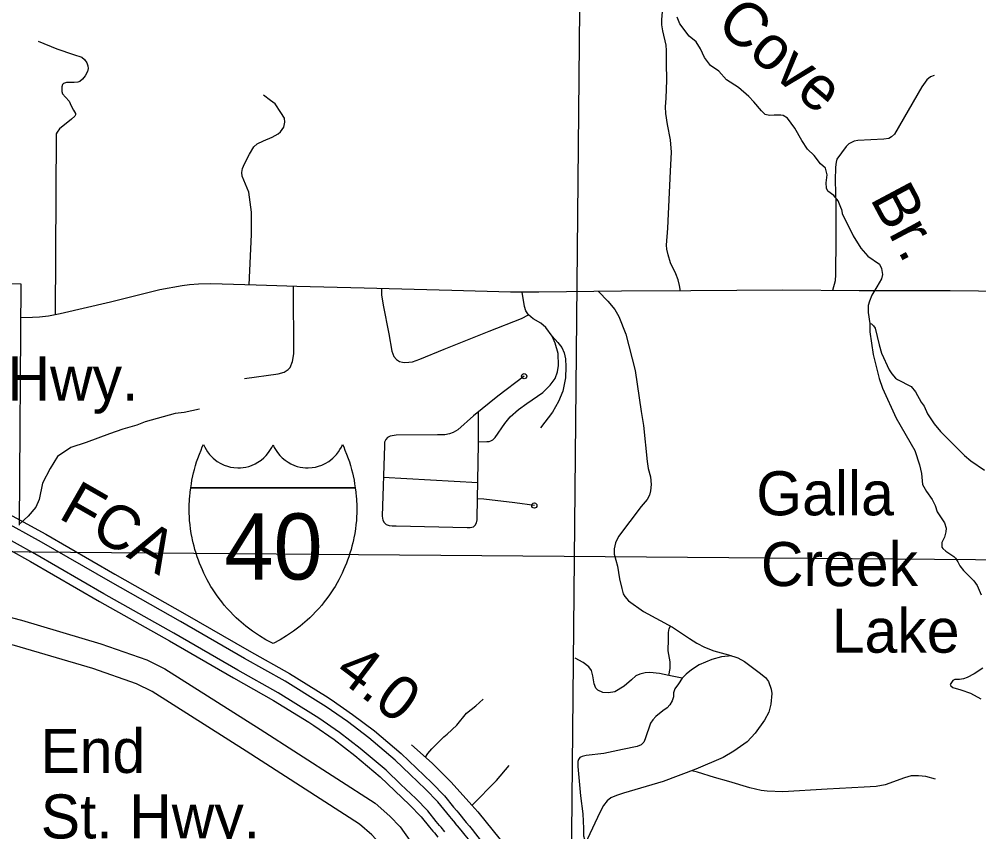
# Model space of a CAD drawing. Extents: x 1374139 to 1377472, y 1168351 to 1170484.
# Drawn here: x 1375599.1 to 1375783.1, y 1169248.4 to 1169404.2 of the extents above; entities that cross this region are included whole.
import ezdxf

# ---------------------------------------------------------------- set-up
doc = ezdxf.new("R2010")
doc.units = 0
doc.layers.add('Default', color=7, linetype='Continuous')

msp = doc.modelspace()

# ---------------------------------------------------------------- linework, layer by layer
at = {"layer": 'Default'}
for points in [[(1375546.74, 1169406.15), (1375546.32, 1169353.56), (1375599.42, 1169353.42), (1375599.06, 1169307.19)], [(1375706.53, 1169406.08), (1375700.78, 1168813.25)], [(1375725.85, 1169352.06), (1375725.68, 1169353.13), (1375725.43, 1169354.18), (1375724.95, 1169355.36), (1375723.98, 1169357.47), (1375723.49, 1169359), (1375723.25, 1169360.08), (1375723.21, 1169360.87), (1375723.42, 1169364.1), (1375723.98, 1169375.03), (1375724.15, 1169378.68), (1375723.98, 1169381.04), (1375723.39, 1169383.99), (1375723.04, 1169386.07), (1375723.01, 1169387.39), (1375723.11, 1169389.02), (1375723.25, 1169392.49), (1375723.18, 1169395.75), (1375723.21, 1169398.15), (1375723.11, 1169399.2), (1375722.49, 1169401.95), (1375722.31, 1169403.06), (1375722.28, 1169404.1), (1375722.42, 1169405.55)], [(1375756.73, 1169367.76), (1375756.11, 1169369.33), (1375755.25, 1169370.36), (1375754.14, 1169371.23), (1375753.85, 1169371.8), (1375753.81, 1169372.79), (1375753.97, 1169374.32), (1375753.64, 1169375.63), (1375752.7, 1169376.46), (1375751.5, 1169378.02), (1375750.19, 1169379.26), (1375749.16, 1169380.9), (1375747.8, 1169383.29), (1375746.36, 1169385.22), (1375745.58, 1169385.68), (1375745.12, 1169385.76), (1375743.85, 1169385.76), (1375742.9, 1169385.72), (1375742.08, 1169385.88), (1375741.38, 1169386.62), (1375739.9, 1169388.35), (1375738.99, 1169389.34), (1375737, 1169391.09), (1375734.69, 1169392.57), (1375733.21, 1169394.22), (1375731.65, 1169395.29), (1375730.5, 1169396.85), (1375729.68, 1169398.5), (1375728.85, 1169399.82), (1375727.54, 1169400.89), (1375725.73, 1169403.28), (1375725.23, 1169404.59)], [(1375602.75, 1169399.98), (1375606.32, 1169398.5), (1375609.49, 1169397.42), (1375611.07, 1169396.92), (1375611.62, 1169396.45), (1375612.05, 1169395.8), (1375612.23, 1169395.22), (1375612.3, 1169394.72), (1375612.19, 1169394.14), (1375611.72, 1169393.31), (1375611.22, 1169392.67), (1375610.75, 1169392.23), (1375610.35, 1169392.09), (1375609.63, 1169392.05), (1375608.16, 1169392.02), (1375607.58, 1169391.87), (1375607.4, 1169391.66), (1375607.26, 1169391.19), (1375607.26, 1169390.32), (1375607.4, 1169389.85), (1375607.94, 1169389.21), (1375608.66, 1169388.48), (1375608.88, 1169387.98), (1375609.17, 1169387.33), (1375609.53, 1169386.75), (1375609.89, 1169386.11), (1375609.89, 1169385.85), (1375609.74, 1169385.56), (1375609.13, 1169385.02), (1375606.79, 1169383.15), (1375606.35, 1169382.54), (1375606.21, 1169382.18)], [(1375774.48, 1169393.36), (1375773.8, 1169393.1), (1375773.12, 1169392.57), (1375772.12, 1169391.21), (1375766.87, 1169382.12), (1375766.33, 1169381.61), (1375765.81, 1169381.32), (1375764.87, 1169381.16), (1375759.88, 1169380.9), (1375759.17, 1169380.8), (1375758.65, 1169380.56), (1375758.15, 1169380.3), (1375757.65, 1169379.77), (1375755.86, 1169377.33), (1375755.71, 1169376.75), (1375755.6, 1169375.83), (1375755.52, 1169373.23), (1375755.63, 1169368.67), (1375755.65, 1169362.04), (1375755.6, 1169355.25), (1375755.52, 1169354.02), (1375755.02, 1169352.15)], [(1375643.16, 1169353.25), (1375643.63, 1169362.92), (1375643.61, 1169367.17), (1375643.1, 1169371.04), (1375641.86, 1169374.07), (1375641.76, 1169374.78), (1375641.89, 1169375.52), (1375642.3, 1169376.46), (1375643.24, 1169378.27), (1375644.08, 1169379.72), (1375644.69, 1169380.29), (1375645.9, 1169380.87), (1375647.61, 1169381.54), (1375648.72, 1169382.18), (1375649.16, 1169382.61), (1375649.8, 1169383.46), (1375650, 1169384.4), (1375649.93, 1169385.17), (1375649.26, 1169386.31), (1375648.15, 1169387.92), (1375647.27, 1169388.56), (1375645.93, 1169389.6)], [(1375606.21, 1169382.18), (1375605.97, 1169347.51)], [(1375756.73, 1169367.76), (1375756.87, 1169366.9), (1375758.97, 1169362.66), (1375760.45, 1169360.31), (1375761.8, 1169358.77), (1375764.02, 1169357.22), (1375764.38, 1169356.41), (1375764.57, 1169355.23), (1375764.39, 1169354.38), (1375763.48, 1169352.86)], [(1375793.77, 1169351.94), (1375777.57, 1169352.13), (1375766.42, 1169352.1), (1375760.13, 1169352.12), (1375745.47, 1169352.21), (1375727.86, 1169352.07), (1375714.56, 1169352.02), (1375698.74, 1169351.85), (1375693.28, 1169351.85), (1375682.05, 1169352.17), (1375665.22, 1169352.64), (1375652.34, 1169352.93), (1375648.49, 1169353.06), (1375644.54, 1169353.21), (1375635.86, 1169353.47), (1375633.47, 1169353.37), (1375631.74, 1169353.26), (1375630.33, 1169353.09), (1375626.04, 1169352.31), (1375616.62, 1169349.96), (1375606.95, 1169347.71), (1375604.73, 1169347.25), (1375603, 1169347.06), (1375601.63, 1169346.96), (1375599.37, 1169346.92)], [(1375642.28, 1169335.3), (1375648.77, 1169336.17), (1375649.9, 1169336.51), (1375650.63, 1169336.99), (1375651.02, 1169337.42), (1375651.5, 1169338.55), (1375651.72, 1169340.02), (1375651.71, 1169352.95)], [(1375668.58, 1169352.55), (1375668.58, 1169351.33), (1375668.84, 1169349.38), (1375669.93, 1169343.89), (1375670.51, 1169340.55), (1375670.94, 1169339.52), (1375671.45, 1169338.94), (1375672, 1169338.57), (1375672.55, 1169338.4), (1375673, 1169338.37), (1375673.81, 1169338.4), (1375674.5, 1169338.51), (1375675.91, 1169339.03), (1375680.56, 1169340.93), (1375689.18, 1169344.38), (1375695.41, 1169346.82), (1375696.74, 1169347.52)], [(1375687.13, 1169323.16), (1375688.77, 1169323.19), (1375689.2, 1169323.25), (1375689.51, 1169323.33), (1375689.89, 1169323.53), (1375690.32, 1169323.97), (1375692.19, 1169326.64), (1375693.22, 1169327.93), (1375694.83, 1169329.34), (1375696.44, 1169330.52), (1375699.47, 1169332.61), (1375700.88, 1169333.99), (1375701.83, 1169335.31), (1375702.31, 1169336.58), (1375702.46, 1169337.78), (1375702.43, 1169340.08), (1375701.85, 1169342.09), (1375701.28, 1169343.39), (1375700.04, 1169345.06), (1375699.12, 1169345.88), (1375697.63, 1169346.74), (1375696.74, 1169347.52), (1375696.19, 1169348.24), (1375695.94, 1169349.07), (1375695.53, 1169351.85)], [(1375710.16, 1169351.97), (1375711.93, 1169350.14), (1375713.27, 1169348.52), (1375714.02, 1169347.21), (1375715.36, 1169343.82), (1375717.17, 1169336.85), (1375718.34, 1169328.95), (1375718.8, 1169326.26), (1375719.45, 1169319.37), (1375719.68, 1169318.03), (1375720.1, 1169316.45), (1375720.24, 1169314.96), (1375720.15, 1169313.75), (1375719.91, 1169312.92), (1375719.5, 1169312.13), (1375718.34, 1169310.78), (1375713.97, 1169305.02), (1375713.41, 1169303.81), (1375713.18, 1169302.65), (1375713.13, 1169301.62), (1375713.78, 1169299.3), (1375714.2, 1169296.88), (1375714.62, 1169295.02), (1375714.9, 1169294.04), (1375715.22, 1169293.53), (1375715.87, 1169292.65), (1375718.8, 1169290.65), (1375724.33, 1169287.63), (1375727.58, 1169285.49), (1375729.02, 1169284.57), (1375730.5, 1169283.82), (1375732.27, 1169283.12), (1375735.06, 1169282.33), (1375736.87, 1169281.78), (1375738.17, 1169281.03), (1375740.95, 1169278.94), (1375742.16, 1169277.97), (1375742.72, 1169277.22), (1375743.28, 1169275.74), (1375743.37, 1169274.9), (1375743.18, 1169272.9), (1375742.81, 1169271.37), (1375741.98, 1169269.79), (1375740.21, 1169267.31), (1375738.68, 1169265.68), (1375736.12, 1169263.87), (1375734.03, 1169262.66), (1375728.83, 1169260.39), (1375722.56, 1169258.06), (1375714.94, 1169255.83), (1375713.6, 1169255.37), (1375712.53, 1169254.9), (1375711.83, 1169254.35), (1375711.09, 1169253.42), (1375710.39, 1169252.12), (1375707.1, 1169245.01)], [(1375763.48, 1169352.86), (1375762.52, 1169351.25), (1375762.07, 1169350.09), (1375761.87, 1169349.29), (1375761.82, 1169347.96), (1375762.17, 1169345.82)], [(1375762.17, 1169345.82), (1375762.15, 1169344.24), (1375762.83, 1169339.88), (1375763.94, 1169335.27), (1375764.61, 1169333.42), (1375767.2, 1169327.71), (1375770.77, 1169321.48), (1375771.67, 1169318.77), (1375772.05, 1169317.06), (1375772.28, 1169314.99), (1375773.04, 1169313.61), (1375774.13, 1169312.09), (1375774.66, 1169310.98), (1375775.05, 1169309.75), (1375776.46, 1169307.61), (1375776.78, 1169306.58), (1375776.76, 1169305.89), (1375776.48, 1169304.91), (1375775.95, 1169303.89), (1375775.99, 1169302.99), (1375776.17, 1169302.69), (1375776.73, 1169302.2), (1375778.29, 1169301.16), (1375778.6, 1169300.84), (1375779.05, 1169300.17), (1375779.43, 1169299.38), (1375780.13, 1169298.49), (1375782.08, 1169296.54), (1375782.76, 1169295.59), (1375783.48, 1169293.84)], [(1375762.17, 1169345.82), (1375762.49, 1169345.79), (1375762.9, 1169345.4), (1375763.19, 1169344.93), (1375763.93, 1169341.77), (1375764.41, 1169340.18), (1375765.86, 1169336.97), (1375766.36, 1169336.16), (1375767.1, 1169335.35), (1375767.49, 1169335.1), (1375770.1, 1169333.78), (1375770.92, 1169332.74), (1375772.01, 1169330.76), (1375772.55, 1169330.01), (1375773.24, 1169328.54), (1375774.47, 1169326.62), (1375775.7, 1169325.11), (1375780.31, 1169320.55), (1375781.55, 1169319.53), (1375784.15, 1169317.75)], [(1375701.28, 1169343.39), (1375702.34, 1169342.21), (1375703.15, 1169341.21), (1375703.58, 1169340.2), (1375703.81, 1169339.05), (1375703.89, 1169337.53), (1375703.84, 1169335.43), (1375703.32, 1169332.87), (1375702.49, 1169330.91), (1375701.34, 1169328.85), (1375699.04, 1169325.86)], [(1375695.9, 1169335.74), (1375690.85, 1169331.91), (1375686.16, 1169328.17), (1375683.17, 1169325.47), (1375682.26, 1169324.95), (1375681.57, 1169324.7), (1375680.68, 1169324.52), (1375679.3, 1169324.52), (1375671.37, 1169324.41), (1375670.22, 1169324.26), (1375669.73, 1169323.98), (1375669.38, 1169323.63), (1375669.15, 1169323.09), (1375669.1, 1169322.45), (1375668.66, 1169308.92), (1375668.78, 1169308.15), (1375669.04, 1169307.72), (1375669.44, 1169307.34), (1375670.01, 1169307.11), (1375670.59, 1169307.06), (1375671.34, 1169307.06), (1375685, 1169306.71), (1375685.55, 1169306.71), (1375686.18, 1169306.88), (1375686.53, 1169307.17), (1375686.76, 1169307.6), (1375686.87, 1169308.18), (1375686.9, 1169308.61), (1375687.13, 1169322.75), (1375687.16, 1169328.97)], [(1375633.63, 1169329.41), (1375630.73, 1169328.79), (1375628.99, 1169328.59), (1375623.24, 1169326.97), (1375621.64, 1169326.32), (1375618.95, 1169325.57), (1375616.39, 1169324.72), (1375611.93, 1169323.05), (1375608.98, 1169322.08), (1375606.41, 1169320.37), (1375605.04, 1169318.02), (1375603.59, 1169315.22), (1375602.93, 1169312.12), (1375602.27, 1169310.63), (1375600.82, 1169308.89), (1375599.3, 1169307.5)], [(1375631.98, 1169314.37), (1375632.1, 1169315.12), (1375632.21, 1169315.79), (1375632.39, 1169316.65), (1375632.52, 1169317.21), (1375632.69, 1169317.87), (1375632.91, 1169318.65), (1375633.11, 1169319.31), (1375633.34, 1169319.98), (1375633.64, 1169320.81), (1375633.95, 1169321.58), (1375634.2, 1169322.19), (1375634.42, 1169322.66), (1375634.65, 1169322.15), (1375634.92, 1169321.66), (1375635.21, 1169321.21), (1375635.6, 1169320.72), (1375635.9, 1169320.38), (1375636.28, 1169320.02), (1375636.65, 1169319.7), (1375637.07, 1169319.4), (1375637.72, 1169319.01), (1375638.39, 1169318.7), (1375639, 1169318.48), (1375639.6, 1169318.33), (1375640.24, 1169318.22), (1375640.99, 1169318.17), (1375641.49, 1169318.18), (1375642.05, 1169318.23), (1375642.55, 1169318.32), (1375643.09, 1169318.45), (1375643.63, 1169318.63), (1375644.36, 1169318.95), (1375644.87, 1169319.24), (1375645.45, 1169319.63), (1375646.01, 1169320.11), (1375646.42, 1169320.52), (1375646.89, 1169321.09), (1375647.27, 1169321.66), (1375647.5, 1169322.07), (1375647.75, 1169322.6)], [(1375647.75, 1169322.6), (1375648, 1169322.07), (1375648.22, 1169321.66), (1375648.61, 1169321.09), (1375649.08, 1169320.52), (1375649.49, 1169320.11), (1375650.05, 1169319.63), (1375650.63, 1169319.24), (1375651.14, 1169318.95), (1375651.87, 1169318.63), (1375652.41, 1169318.45), (1375652.95, 1169318.32), (1375653.45, 1169318.23), (1375654.01, 1169318.18), (1375654.51, 1169318.17), (1375655.26, 1169318.22), (1375655.9, 1169318.33), (1375656.5, 1169318.48), (1375657.11, 1169318.7), (1375657.78, 1169319.01), (1375658.43, 1169319.4), (1375658.84, 1169319.7), (1375659.22, 1169320.02), (1375659.6, 1169320.38), (1375659.9, 1169320.72), (1375660.29, 1169321.21), (1375660.58, 1169321.66), (1375660.85, 1169322.15), (1375661.08, 1169322.66), (1375661.3, 1169322.19), (1375661.55, 1169321.58), (1375661.86, 1169320.81), (1375662.16, 1169319.98), (1375662.39, 1169319.31), (1375662.59, 1169318.65), (1375662.81, 1169317.87), (1375662.98, 1169317.21), (1375663.11, 1169316.65), (1375663.29, 1169315.79), (1375663.4, 1169315.12), (1375663.52, 1169314.37)], [(1375668.9, 1169316.4), (1375687.01, 1169315.34)], [(1375647.75, 1169284.49), (1375646.37, 1169285.23), (1375645.15, 1169285.96), (1375643.81, 1169286.86), (1375642.57, 1169287.81), (1375641.2, 1169288.97), (1375640.69, 1169289.45), (1375640.11, 1169290.01), (1375639.58, 1169290.57), (1375638.99, 1169291.21), (1375638.41, 1169291.88), (1375637.93, 1169292.48), (1375637.41, 1169293.15), (1375636.93, 1169293.81), (1375636.52, 1169294.41), (1375636.16, 1169294.97), (1375635.86, 1169295.45), (1375635.47, 1169296.12), (1375635.16, 1169296.68), (1375634.83, 1169297.32), (1375634.5, 1169297.99), (1375634.21, 1169298.6), (1375633.95, 1169299.2), (1375633.68, 1169299.87), (1375633.44, 1169300.49), (1375633.22, 1169301.13), (1375633, 1169301.81), (1375632.79, 1169302.5), (1375632.61, 1169303.16), (1375632.45, 1169303.79), (1375632.32, 1169304.34), (1375632.24, 1169304.76), (1375632.09, 1169305.56), (1375631.94, 1169306.49), (1375631.85, 1169307.26), (1375631.77, 1169308.08), (1375631.73, 1169308.74), (1375631.7, 1169309.57), (1375631.69, 1169310.35), (1375631.71, 1169311.22), (1375631.73, 1169311.79), (1375631.76, 1169312.31), (1375631.79, 1169312.64), (1375631.87, 1169313.5), (1375631.98, 1169314.37)], [(1375631.98, 1169314.37), (1375663.52, 1169314.37)], [(1375663.52, 1169314.37), (1375631.98, 1169314.37)], [(1375663.52, 1169314.37), (1375663.63, 1169313.5), (1375663.71, 1169312.64), (1375663.74, 1169312.31), (1375663.77, 1169311.79), (1375663.79, 1169311.22), (1375663.81, 1169310.35), (1375663.8, 1169309.57), (1375663.77, 1169308.74), (1375663.73, 1169308.08), (1375663.65, 1169307.26), (1375663.56, 1169306.49), (1375663.41, 1169305.56), (1375663.26, 1169304.76), (1375663.18, 1169304.34), (1375663.05, 1169303.79), (1375662.89, 1169303.16), (1375662.71, 1169302.5), (1375662.5, 1169301.81), (1375662.28, 1169301.13), (1375662.05, 1169300.49), (1375661.82, 1169299.87), (1375661.55, 1169299.2), (1375661.29, 1169298.6), (1375661, 1169297.99), (1375660.67, 1169297.32), (1375660.34, 1169296.68), (1375660.03, 1169296.12), (1375659.64, 1169295.45), (1375659.34, 1169294.97), (1375658.98, 1169294.41), (1375658.57, 1169293.81), (1375658.09, 1169293.15), (1375657.57, 1169292.48), (1375657.09, 1169291.88), (1375656.51, 1169291.21), (1375655.92, 1169290.57), (1375655.39, 1169290.01), (1375654.81, 1169289.45), (1375654.3, 1169288.97), (1375652.93, 1169287.81), (1375651.68, 1169286.86), (1375650.35, 1169285.96), (1375649.13, 1169285.23), (1375647.75, 1169284.49)], [(1375697.85, 1169310.95), (1375694.12, 1169311.45), (1375688.14, 1169312.14), (1375686.96, 1169312.25)], [(1375596.34, 1169309.76), (1375604.2, 1169305.43), (1375617.45, 1169297.76), (1375630.86, 1169290.2), (1375643.15, 1169283.1), (1375650.93, 1169278.75), (1375657.83, 1169274.45), (1375658.91, 1169273.75), (1375663, 1169270.92), (1375667.19, 1169267.74), (1375672.3, 1169263.42), (1375675.25, 1169260.6), (1375678.17, 1169257.8), (1375680.62, 1169255.27), (1375682.35, 1169253.15), (1375682.96, 1169252.43), (1375683.3, 1169252.04), (1375684.06, 1169251.1)], [(1375682.72, 1169250.04), (1375682, 1169250.95), (1375681.67, 1169251.32), (1375681.05, 1169252.07), (1375679.35, 1169254.13), (1375676.97, 1169256.6), (1375674.07, 1169259.37), (1375671.16, 1169262.15), (1375666.12, 1169266.41), (1375662, 1169269.55), (1375657.96, 1169272.34), (1375656.92, 1169273.02), (1375650.06, 1169277.29), (1375642.31, 1169281.62), (1375630.02, 1169288.72), (1375616.61, 1169296.29), (1375603.36, 1169303.95), (1375595.5, 1169308.29)], [(1375680.69, 1169248.42), (1375680.01, 1169249.28), (1375679.7, 1169249.62), (1375679.04, 1169250.4), (1375677.4, 1169252.41), (1375675.14, 1169254.76), (1375672.28, 1169257.49), (1375669.43, 1169260.22), (1375664.49, 1169264.38), (1375660.48, 1169267.44), (1375656.52, 1169270.18), (1375655.52, 1169270.82), (1375648.74, 1169275.05), (1375641.02, 1169279.36), (1375628.73, 1169286.46), (1375615.32, 1169294.03), (1375602.08, 1169301.68), (1375594.21, 1169306.03)], [(1375924.39, 1169299.41), (1375198.69, 1169305.24)], [(1375593.37, 1169304.55), (1375601.24, 1169300.2), (1375614.47, 1169292.55), (1375627.89, 1169284.98), (1375640.18, 1169277.89), (1375647.87, 1169273.59), (1375654.61, 1169269.39), (1375655.57, 1169268.77), (1375659.48, 1169266.07), (1375663.43, 1169263.06), (1375668.29, 1169258.95), (1375671.1, 1169256.26), (1375673.94, 1169253.55), (1375676.13, 1169251.27), (1375677.74, 1169249.32), (1375678.41, 1169248.51), (1375678.71, 1169248.18), (1375679.36, 1169247.36)], [(1375582.23, 1169293.42), (1375599.56, 1169288.96), (1375614.74, 1169284.46), (1375623.57, 1169281.39), (1375627.03, 1169279.62), (1375645.31, 1169268.09), (1375667.32, 1169253.87), (1375670.13, 1169251.42), (1375672.12, 1169249.33), (1375681.28, 1169236.46), (1375693.31, 1169219.15), (1375703.09, 1169205.04), (1375708.96, 1169197.88), (1375713.03, 1169193.87), (1375719.04, 1169189.03), (1375727.51, 1169183.26)], [(1375724.53, 1169179.24), (1375716.06, 1169185.01), (1375709.7, 1169190.14), (1375705.26, 1169194.51), (1375699.09, 1169202.03), (1375689.2, 1169216.3), (1375677.19, 1169233.58), (1375668.25, 1169246.14), (1375666.67, 1169247.8), (1375664.31, 1169249.86), (1375642.62, 1169263.88), (1375624.56, 1169275.27), (1375621.6, 1169276.78), (1375613.21, 1169279.7), (1375598.22, 1169284.14), (1375581.02, 1169288.57)], [(1375726.21, 1169277.88), (1375723.65, 1169278.39), (1375723.87, 1169279.7), (1375723.87, 1169281), (1375723.52, 1169283.09), (1375723.57, 1169285.35), (1375723.57, 1169286.61), (1375723.7, 1169287.35), (1375723.93, 1169287.85)], [(1375723.65, 1169278.39), (1375721.83, 1169278.74), (1375720, 1169278.92), (1375719.09, 1169278.87), (1375718.05, 1169278.65), (1375717.31, 1169278.31), (1375716.48, 1169277.52), (1375715.09, 1169276.31), (1375713.26, 1169275.22), (1375712.09, 1169275.04), (1375710.96, 1169275.09), (1375710, 1169275.57), (1375709.66, 1169275.96), (1375709.31, 1169276.74), (1375709.05, 1169278.31), (1375708.83, 1169279.31), (1375708.31, 1169280.05), (1375707.18, 1169280.83), (1375705.7, 1169281.7)], [(1375735.68, 1169282.14), (1375733.72, 1169281.92), (1375731.85, 1169281.44), (1375729.46, 1169280.39), (1375727.98, 1169279.48), (1375726.98, 1169278.65), (1375726.2, 1169277.87), (1375725.46, 1169276.78), (1375724.77, 1169275.78), (1375724.55, 1169275.04), (1375724.51, 1169274.26), (1375724.29, 1169273.52), (1375723.85, 1169272.74), (1375723.29, 1169272.17), (1375722.51, 1169271.61), (1375721.12, 1169270.48), (1375720.55, 1169269.87), (1375720.12, 1169269.26), (1375719.07, 1169266.22), (1375718.81, 1169265.61), (1375718.33, 1169265.09), (1375717.59, 1169264.78), (1375714.73, 1169264.17), (1375711.16, 1169263.39), (1375707.81, 1169263)], [(1375783.8, 1169279.77), (1375782.16, 1169278.66), (1375780.8, 1169277.97), (1375780.09, 1169277.73), (1375779.33, 1169277.59), (1375778.43, 1169277.57), (1375778.05, 1169277.42), (1375777.57, 1169276.65), (1375777.68, 1169276.39), (1375778.09, 1169276.04), (1375779.64, 1169275.63), (1375781.45, 1169274.99), (1375783.42, 1169273.92)], [(1375681.14, 1169267.11), (1375682.97, 1169268.83), (1375684.86, 1169271.16), (1375686.66, 1169272.54), (1375688.05, 1169273.82)], [(1375677, 1169262.7), (1375677.4, 1169263.39), (1375678.2, 1169264.33), (1375680.53, 1169266.61), (1375681.14, 1169267.11)], [(1375674.28, 1169265.08), (1375678.28, 1169261.58), (1375681.93, 1169257.89), (1375685.88, 1169253.54), (1375687.04, 1169252.21), (1375691.3, 1169246.95), (1375694.39, 1169242.68), (1375696.26, 1169239.85), (1375697.95, 1169237.2), (1375699.99, 1169234.19)], [(1375707.81, 1169263), (1375706.99, 1169262.82), (1375706.6, 1169262.65), (1375706.29, 1169262.26), (1375706.21, 1169261.87), (1375706.21, 1169260.91), (1375706.68, 1169255.28), (1375707.12, 1169251.84), (1375707.25, 1169249.06), (1375707.29, 1169247.63), (1375707.47, 1169247.02), (1375707.77, 1169246.46)], [(1375685.92, 1169253.5), (1375690.6, 1169258.27), (1375693.01, 1169261.13)], [(1375774.75, 1169258.51), (1375772.91, 1169258.99), (1375771.48, 1169259.16), (1375770.12, 1169259.11), (1375768.82, 1169258.75), (1375765.08, 1169257.44), (1375763.36, 1169257.09), (1375761.05, 1169256.97), (1375753.99, 1169256.61), (1375745.46, 1169256.08), (1375742.51, 1169256.18), (1375741.35, 1169256.33), (1375739.19, 1169256.84), (1375735.13, 1169258.02), (1375732.37, 1169258.79), (1375729.11, 1169259.83), (1375728.05, 1169260.1)], [(1375683.99, 1169251.17), (1375684.81, 1169250.21), (1375685.39, 1169249.5), (1375685.93, 1169248.84), (1375686.57, 1169248.03), (1375687.45, 1169246.88), (1375689.02, 1169244.82), (1375690.05, 1169243.44), (1375692.28, 1169240.34), (1375693.95, 1169237.54), (1375694.53, 1169236.66), (1375695.03, 1169235.94), (1375695.59, 1169235.1), (1375696, 1169234.52), (1375696.32, 1169233.97), (1375696.51, 1169233.68), (1375696, 1169233.34), (1375695.09, 1169232.74)], [(1375695.09, 1169232.74), (1375694.88, 1169233.08), (1375694.57, 1169233.59), (1375694.19, 1169234.14), (1375693.63, 1169234.98), (1375693.13, 1169235.71), (1375692.51, 1169236.63), (1375690.86, 1169239.4), (1375688.68, 1169242.44), (1375687.67, 1169243.8), (1375686.1, 1169245.85), (1375685.23, 1169246.98), (1375684.6, 1169247.78), (1375684.07, 1169248.43), (1375683.5, 1169249.12), (1375682.7, 1169250.07)]]:
    msp.add_lwpolyline(points, dxfattribs=at)
for centre in [(1375695.9, 1169335.74), (1375697.85, 1169310.95)]:
    msp.add_circle(centre, 0.5, dxfattribs=at)

# ---------------------------------------------------------------- texts
for s, rotation, p in [('Cove', 319.77, (1375732.39, 1169402.67)), ('Br.', 298.0637, (1375762.12, 1169369.8)), ('FCA', 330.2626, (1375606.38, 1169308.65)), ('4.0', 322.9986, (1375659.23, 1169278.34))]:
    msp.add_text(s, height=8.448, rotation=rotation, dxfattribs=at).set_placement(p)
for s, height, p in [('St. Hwy.', 8.448, (1375579.9, 1169331.07)), ('Galla', 8.448, (1375740.4, 1169309.07)), ('40', 12.672, (1375638.42, 1169296.76)), ('Creek', 8.448, (1375741.28, 1169295.5)), ('Lake', 8.448, (1375754.87, 1169282.74)), ('End', 8.448, (1375603.16, 1169259.69)), ('St. Hwy.', 8.448, (1375603.23, 1169247.13))]:
    msp.add_text(s, height=height, dxfattribs=at).set_placement(p)

doc.saveas('drawing.dxf')
